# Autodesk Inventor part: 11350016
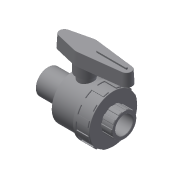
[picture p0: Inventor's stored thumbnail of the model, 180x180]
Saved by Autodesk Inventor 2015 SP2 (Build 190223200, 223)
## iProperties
Created: 2017-11
Part Number: 11350016
Material: Generic
Description: PLASSON 1/NUT VALVE CEM. PVC 16
Document SubType Name: Modeling
Designer: KIM
Density: 1 g/cm^3
Appearance: Default
Author: KIM
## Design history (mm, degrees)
derived "113500.ipt"
feature "Solid1::113500.ipt"
tag "TaggingFeature1"
body "Solid1"
other parameters: "d0" = 69, "d2" = 45, "d4" = 12.8, "d8" = 40.5, "d13" = 0.48, "d25" = 0.32, "d26" = 0.48, "d29" = 10.5, "d30" = 0, "d35" = 0.48, "d39" = 22.5, "d45" = 360 deg, "d47" = 0.32, "d50" = 24.75, "d51" = 13.5, "d53" = 0, "d55" = 3.2, "d56" = 1.6, "d57" = 9.8, "d58" = 0, "d59" = 0.48, "d63" = 18, "d64" = 45, "d66" = 65, "d68" = 9, "d69" = 19.5, "d70" = 11.25, "d71" = 3 deg, "d73" = 0.9, "d74" = 26, "d75" = 1.35, "d76" = 0, "d77" = 0.32, "d78" = 16, "d79" = 14, "d80" = 45, "d81" = 14, "d82" = 43.2, "d83" = 9.8, "d84" = 22.4, "d85" = 16, "d86" = 22.4, "d87" = 120 deg, "d88" = 14, "d90" = 360 deg, "d92" = 6.75, "d95" = 3.375, "d_" = 16, "l_" = 14, "H_" = 69, "K_" = 45, "F_" = 45, "J_" = 65, "d67" = 18, "d72" = 4.5
